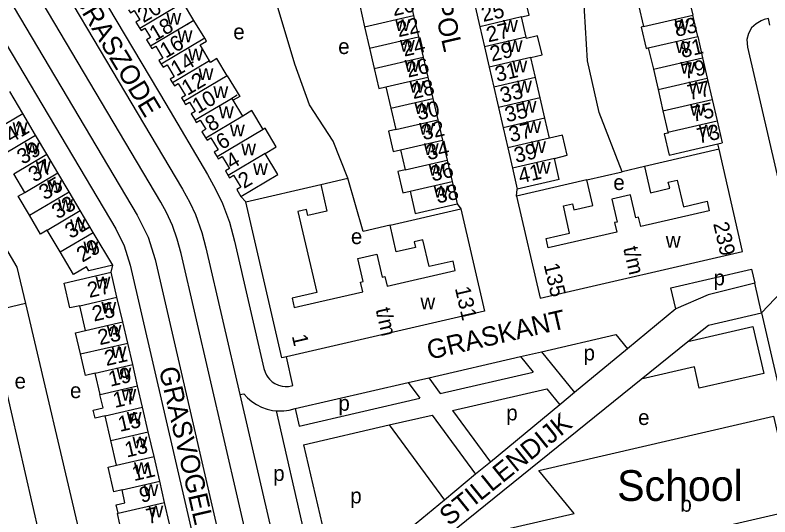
# Model space of a CAD drawing. Extents: x 155696 to 157795, y 382328 to 384028.
# Drawn here: x 156827.2 to 157023.6, y 383450.5 to 383581.1 of the extents above; entities that cross this region are included whole.
import ezdxf

# ---------------------------------------------------------------- set-up
doc = ezdxf.new("R2010")
doc.units = 0
for name, color, linetype in [('BLT_Basislijn', 7, 'Continuous'), ('BLT_Bebouwing', 7, 'Continuous'), ('BLT_Bebouwing_beschrifting', 7, 'Continuous'), ('BLT_Centroide', 7, 'Continuous'), ('BLT_Huisnummer', 7, 'Continuous'), ('BLT_Huisnummer_ tussenligend', 7, 'Continuous'), ('BLT_Huisnummer_reeks', 7, 'Continuous'), ('BLT_Onderverdeling_panden', 7, 'Continuous'), ('BLT_Straatnaam', 7, 'Continuous'), ('BLT_Vlakafsluiter', 7, 'Continuous')]:
    doc.layers.add(name, color=color, linetype=linetype)

msp = doc.modelspace()

# ---------------------------------------------------------------- linework, layer by layer
at = {"layer": 'BLT_Basislijn'}
for p, q in [((157010.4, 383546.2), (157010.08, 383547.6)), ((156991.02, 383541.71), (156985.17, 383540.36)), ((156813.06, 383540.07), (156827.64, 383515.53)), ((156976.01, 383538.25), (156985.17, 383540.36)), ((156906.74, 383537.03), (156913.76, 383538.66)), ((156917.76, 383524.82), (156913.76, 383538.66)), ((156957.68, 383534.02), (156957.88, 383535.82)), ((156887.21, 383532.52), (156885.94, 383533.92)), ((156942.23, 383532.02), (156943.16, 383530.67)), ((156924.78, 383526.43), (156917.76, 383524.82)), ((156852.19, 383514.18), (156852.6, 383515.97)), ((156827.64, 383515.53), (156829.86, 383506.04)), ((157021.46, 383503.61), (157019.76, 383511.33)), ((156829.86, 383506.04), (156820.23, 383503.79)), ((156829.86, 383506.04), (156847.51, 383431.01)), ((156837.46, 383428.77), (156820.23, 383503.79)), ((156958.72, 383492.19), (156962.01, 383488.17)), ((156964.15, 383493.44), (156972.82, 383482.87)), ((156937.81, 383482.58), (156962.01, 383488.17)), ((156934.82, 383486.67), (156937.81, 383482.58)), ((156929.51, 383485.44), (156932.51, 383481.35)), ((156941.03, 383478.19), (156965.55, 383483.85)), ((156965.55, 383483.85), (156968.96, 383479.68)), ((156901.15, 383474.11), (156932.51, 383481.35)), ((156900.1, 383478.65), (156901.15, 383474.11)), ((156895.09, 383478.09), (156906.54, 383428.52)), ((156924.57, 383474.39), (156935.73, 383476.96)), ((156935.73, 383476.96), (156947.03, 383461.55)), ((156941.03, 383478.19), (156950.89, 383464.75)), ((156902.27, 383469.24), (156924.57, 383474.39)), ((156924.57, 383474.39), (156938.91, 383454.84)), ((156902.27, 383469.24), (156910.94, 383431.72))]:
    msp.add_line(p, q, dxfattribs=at)
for points in [[(156985.17, 383540.36), (156979.21, 383555.75), (156976.12, 383569.24), (156975.14, 383586.64), (156972.66, 383601.42), (156967.79, 383615.59), (156962.86, 383637.18)], [(156819.05, 383622.9), (156870.75, 383535.77), (156872.62, 383532.3), (156874.14, 383529.17), (156875.78, 383524.53), (156876.84, 383520.56)], [(156830.06, 383623.03), (156830.96, 383618.27), (156832.24, 383615.56), (156866.39, 383558), (156877.28, 383539.64), (156879.37, 383535.8), (156881.18, 383532.03), (156882.95, 383527.19), (156884.25, 383522.27), (156891.92, 383489.07), (156892.22, 383488.12), (156892.6, 383487.38), (156892.95, 383486.88), (156893.38, 383486.33), (156894.12, 383485.66), (156894.79, 383485.21), (156895.73, 383484.76), (156896.68, 383484.52), (156897.5, 383484.43), (156898.35, 383484.44), (156899.11, 383484.58), (156899.5, 383484.67), (156897.77, 383492.17)], [(156983.21, 383030.72), (156967.38, 383099.24), (156870.41, 383519.08), (156869.37, 383522.79), (156868.15, 383526.38), (156866.54, 383529.72), (156865.07, 383532.4), (156812.59, 383620.85)], [(156804.51, 383617.81), (156812.22, 383604.81), (156813.61, 383602.86), (156815.47, 383601.09), (156816.82, 383599.81), (156817.73, 383598.46), (156858.93, 383529.03), (156861.8, 383523.32), (156863.59, 383517.5), (156885.15, 383424.18), (156889.03, 383407.35)], [(156800.07, 383613.67), (156800.58, 383613.17), (156801.11, 383612.63), (156801.9, 383611.42), (156807.49, 383602), (156810.35, 383597.97), (156853.37, 383525.46), (156855.54, 383521.06), (156857.16, 383516.02), (156880.47, 383415.1), (156880.62, 383413.68), (156880.33, 383411.87), (156879.52, 383410.29), (156878.8, 383409.4), (156877.87, 383408.71), (156877.29, 383411.17)], [(156913.76, 383538.66), (156909.99, 383548.33), (156903.82, 383557.78), (156899.97, 383568.38), (156893.8, 383589.01)], [(157023.66, 383578.52), (157023.27, 383580.23), (157022.19, 383579.96), (157021.34, 383579.68), (157020.04, 383578.87), (157018.83, 383577.79), (157018.05, 383576.3), (157017.68, 383574.81), (157017.8, 383572.79), (157028.71, 383525.55)], [(156876.84, 383520.56), (156885.68, 383482.29)], [(156999.14, 383504.62), (156997.86, 383510.15), (157018.83, 383515), (157019.76, 383511.33)], [(157019.76, 383511.33), (157007.58, 383508.26), (156999.14, 383504.62)], [(156999.14, 383504.62), (156986.6, 383494.26)], [(157007.65, 383500.41), (157021.46, 383503.61)], [(157021.46, 383503.61), (157033.62, 383450.98)], [(157002.3, 383496.1), (157019.22, 383500.01), (157022.03, 383487.83), (157005.27, 383483.96), (157003.99, 383489.51), (156990.17, 383486.32)], [(157002.3, 383496.1), (157007.65, 383500.41)], [(156964.15, 383493.44), (156983.57, 383497.93), (156986.6, 383494.26)], [(156990.17, 383486.32), (157002.3, 383496.1)], [(156986.6, 383494.26), (156972.82, 383482.87)], [(156934.82, 383486.67), (156958.72, 383492.19)], [(156958.72, 383492.19), (156964.15, 383493.44)], [(156911.34, 383422.73), (156990.17, 383486.32)], [(156929.51, 383485.44), (156934.82, 383486.67)], [(156900.1, 383478.65), (156929.51, 383485.44)], [(156885.68, 383482.29), (156886.75, 383482.53), (156887.69, 383481.48), (156888.78, 383480.53), (156890, 383479.7), (156891.33, 383479.02), (156892.74, 383478.51), (156894.2, 383478.18), (156895.09, 383478.09)], [(156885.68, 383482.29), (156898.85, 383425.26)], [(156972.82, 383482.87), (156968.96, 383479.68)], [(156895.09, 383478.09), (156895.67, 383478.04), (156897.12, 383478.08), (156898.51, 383478.28)], [(156898.51, 383478.28), (156900.1, 383478.65)], [(156968.96, 383479.68), (156950.89, 383464.75)], [(156950.89, 383464.75), (156947.03, 383461.55)], [(156947.03, 383461.55), (156938.91, 383454.84)], [(156938.91, 383454.84), (156910.94, 383431.72)]]:
    msp.add_lwpolyline(points, dxfattribs=at)
at = {"layer": 'BLT_Bebouwing'}
for p, q in [((156929.63, 383586.59), (156930.91, 383581.04)), ((157002.28, 383586.66), (157003.56, 383581.11)), ((156916.86, 383583.64), (156918.14, 383578.08)), ((156946.89, 383583.38), (156948.11, 383578.12)), ((156989.46, 383583.7), (156990.71, 383578.14)), ((156930.91, 383581.04), (156932.19, 383575.48)), ((156960.24, 383575.38), (156959.02, 383580.64)), ((157004.85, 383575.55), (157003.56, 383581.11)), ((156873.52, 383579.6), (156871.84, 383578.6)), ((156876.52, 383575.1), (156873.73, 383579.73)), ((156918.14, 383578.08), (156919.41, 383572.53)), ((156948.11, 383578.12), (156949.32, 383572.86)), ((156932.19, 383575.48), (156933.41, 383570.22)), ((157004.85, 383575.55), (157006.13, 383570)), ((156949.32, 383572.86), (156950.54, 383567.6)), ((156919.41, 383572.53), (156920.62, 383567.27)), ((156991.41, 383572.44), (156991.98, 383572.58)), ((156933.41, 383570.22), (156934.63, 383564.96)), ((156962.67, 383564.86), (156961.45, 383570.12)), ((157006.13, 383570), (157007.35, 383564.74)), ((156950.54, 383567.6), (156951.75, 383562.34)), ((156993.31, 383567.04), (156994.53, 383561.78)), ((156934.63, 383564.96), (156935.92, 383559.41)), ((156963.88, 383559.59), (156962.67, 383564.86)), ((157007.35, 383564.74), (157008.63, 383559.18)), ((156829.14, 383555.52), (156825.77, 383561.2)), ((156923.71, 383562.44), (156925, 383556.88)), ((156951.75, 383562.34), (156952.71, 383558.18)), ((156994.53, 383561.78), (156995.78, 383556.21)), ((156885, 383560.25), (156883.32, 383559.25)), ((156886.44, 383554.82), (156883.96, 383558.95)), ((156935.92, 383559.41), (156937.19, 383553.85)), ((156965.1, 383554.33), (156963.88, 383559.59)), ((157008.63, 383559.18), (157009.91, 383553.63)), ((156925, 383556.88), (156926.28, 383551.33)), ((156952.71, 383558.18), (156952.97, 383557.07)), ((156952.97, 383557.07), (156953.93, 383552.92)), ((156832.51, 383549.85), (156829.14, 383555.52)), ((156995.78, 383556.21), (156997.06, 383550.66)), ((156937.19, 383553.85), (156938.41, 383548.59)), ((156966.31, 383549.07), (156965.1, 383554.33)), ((157009.91, 383553.63), (157011.24, 383547.87)), ((156953.93, 383552.92), (156954.19, 383551.81)), ((156954.19, 383551.81), (156955.4, 383546.55)), ((156835.42, 383544.94), (156832.51, 383549.85)), ((156938.41, 383548.59), (156939.62, 383543.33)), ((157000.33, 383545.35), (157010.08, 383547.6)), ((157010.08, 383547.6), (157011.24, 383547.87)), ((156927.49, 383546.07), (156928.71, 383540.81)), ((156955.4, 383546.55), (156956.62, 383541.29)), ((157010.4, 383546.2), (156991.02, 383541.71)), ((156838.32, 383540.04), (156835.42, 383544.94)), ((156939.62, 383543.33), (156940.9, 383537.77)), ((156968.79, 383538.34), (156967.53, 383543.81)), ((156956.62, 383541.29), (156957.88, 383535.82)), ((156829.72, 383534.94), (156826.82, 383539.84)), ((156841.23, 383535.14), (156838.32, 383540.04)), ((156940.9, 383537.77), (156942.23, 383532.02)), ((156976.01, 383538.25), (156957.68, 383534.02)), ((156968.79, 383538.34), (156957.88, 383535.82)), ((156887.21, 383532.52), (156906.74, 383537.03)), ((156844.14, 383530.24), (156841.23, 383535.14)), ((156929.99, 383535.25), (156931.32, 383529.49)), ((156931.32, 383529.5), (156942.23, 383532.02)), ((156847.51, 383524.56), (156844.14, 383530.24)), ((156924.78, 383526.43), (156943.16, 383530.67)), ((156838.91, 383519.46), (156835.54, 383525.14)), ((156852.6, 383515.97), (156847.51, 383524.56)), ((156853.69, 383507.69), (156852.19, 383514.18)), ((156855.23, 383501.28), (156853.69, 383507.69)), ((156845.48, 383499.03), (156844, 383505.46)), ((156856.51, 383495.72), (156855.23, 383501.28)), ((156857.79, 383490.17), (156856.51, 383495.72)), ((156859.07, 383484.61), (156857.79, 383490.17)), ((156849.33, 383482.36), (156848.05, 383487.92)), ((156860.36, 383479.06), (156859.07, 383484.61)), ((156861.84, 383472.63), (156860.36, 383479.06)), ((156852.1, 383470.38), (156850.61, 383476.81)), ((156863.33, 383466.2), (156861.84, 383472.63)), ((156864.81, 383459.77), (156863.33, 383466.2)), ((156866.09, 383454.21), (156864.81, 383459.77)), ((156867.38, 383448.66), (156866.09, 383454.21)), ((156853.78, 383451.37), (156854.01, 383451.42))]:
    msp.add_line(p, q, dxfattribs=at)
for points in [[(156959.02, 383580.64), (156960.95, 383581.08), (156959.73, 383586.35)], [(156856.69, 383582.52), (156857.18, 383581.7), (156858.2, 383582.32), (156859.65, 383579.91), (156858.63, 383579.3), (156859.63, 383577.64)], [(156873.73, 383579.73), (156871.03, 383584.22), (156869.38, 383583.22), (156869.29, 383583.37)], [(156859.63, 383577.64), (156859.97, 383577.08), (156860.98, 383577.69), (156862.43, 383575.29), (156861.41, 383574.67), (156862.41, 383573)], [(156990.71, 383578.14), (156990.14, 383578.01), (156991.41, 383572.44)], [(156877.8, 383569.23), (156875.32, 383573.35), (156876.98, 383574.35), (156876.52, 383575.1)], [(156961.45, 383570.12), (156964.34, 383570.78), (156963.19, 383575.72), (156960.32, 383575.06), (156960.24, 383575.38)], [(156862.41, 383573), (156862.74, 383572.44), (156863.77, 383573.06), (156865.65, 383569.94), (156864.61, 383569.32), (156865.19, 383568.38)], [(156991.98, 383572.58), (156993.31, 383567.04)], [(156882.4, 383565.33), (156879.69, 383569.82), (156878.04, 383568.83), (156877.8, 383569.23)], [(156865.19, 383568.38), (156865.69, 383567.57), (156866.71, 383568.18), (156868.58, 383565.08), (156867.54, 383564.45), (156868.13, 383563.49)], [(156920.62, 383567.27), (156921.83, 383562.01), (156923.71, 383562.44)], [(156882.4, 383565.33), (156885.64, 383559.95), (156883.96, 383558.95)], [(156868.13, 383563.49), (156868.62, 383562.7), (156869.64, 383563.31), (156871.52, 383560.2), (156870.48, 383559.57), (156871.06, 383558.61)], [(156871.06, 383558.61), (156871.55, 383557.81), (156872.58, 383558.43), (156874.03, 383556.03), (156872.99, 383555.4), (156874.01, 383553.73)], [(156891.73, 383551.34), (156888.79, 383556.26), (156886.44, 383554.82)], [(156874.01, 383553.73), (156874.34, 383553.18), (156875.37, 383553.8), (156876.82, 383551.39), (156875.76, 383550.75), (156876.78, 383549.09)], [(156892.3, 383545.05), (156895.16, 383546.79), (156892.25, 383551.65), (156891.73, 383551.34)], [(156926.28, 383551.33), (156924.39, 383550.89), (156925.6, 383545.63), (156927.49, 383546.07)], [(156876.78, 383549.09), (156877.12, 383548.55), (156878.15, 383549.18), (156880.04, 383546.05), (156878.99, 383545.42), (156879.73, 383544.22)], [(156967.53, 383543.81), (156970.85, 383544.62), (156969.65, 383549.86), (156966.31, 383549.07)], [(156997.06, 383550.66), (156997.12, 383550.43), (156996.14, 383550.21), (156997.41, 383544.67), (157000.33, 383545.35)], [(156957.68, 383534.02), (156963.83, 383507.42), (157016.54, 383519.6), (157010.4, 383546.2)], [(156879.73, 383544.22), (156880.06, 383543.68), (156881.09, 383544.3), (156882.98, 383541.16), (156881.95, 383540.54), (156882.67, 383539.33)], [(156885.94, 383533.92), (156895.55, 383539.63), (156892.3, 383545.05)], [(156991.02, 383541.71), (156992.59, 383534.89), (156997.56, 383536.04), (156997.2, 383537.6), (156999.54, 383538.14), (157001.14, 383531.22), (157007.28, 383532.64), (157007.84, 383530.2), (156990.01, 383526.08), (156989.45, 383528.52), (156988.76, 383528.36), (156987.39, 383534.31), (156982.52, 383533.18), (156983.89, 383527.24), (156983.21, 383527.08), (156983.77, 383524.64), (156965.94, 383520.52), (156965.38, 383522.96), (156971.52, 383524.38), (156969.89, 383531.44), (156972.22, 383531.98), (156972.58, 383530.42), (156977.55, 383531.57), (156976.01, 383538.25)], [(156882.67, 383539.33), (156883, 383538.79), (156884.03, 383539.41), (156885.9, 383536.31), (156884.86, 383535.68), (156885.94, 383533.92)], [(156928.71, 383540.81), (156926.81, 383540.37), (156928.1, 383534.82), (156929.99, 383535.25)], [(156906.74, 383537.03), (156908.35, 383530.07), (156903.37, 383528.92), (156902.99, 383530.54), (156900.78, 383530.02), (156905.67, 383508.88), (156899.25, 383507.4), (156899.82, 383504.96), (156906.24, 383506.45), (156917.65, 383509.08), (156917.06, 383511.61), (156917.74, 383511.77), (156916.36, 383517.76), (156921.36, 383518.91), (156922.74, 383512.92), (156923.43, 383513.08), (156924.01, 383510.54), (156941.74, 383514.63), (156941.18, 383517.07), (156934.95, 383515.63), (156933.33, 383522.64), (156931.04, 383522.12), (156931.38, 383520.64), (156926.38, 383519.48), (156924.78, 383526.43)], [(156830.88, 383529), (156827.94, 383533.96), (156829.72, 383534.94)], [(156897.77, 383492.16), (156896.6, 383491.89), (156887.21, 383532.52)], [(156943.16, 383530.67), (156949.31, 383504.07), (156897.77, 383492.16)], [(156835.54, 383525.14), (156833.79, 383524.1), (156830.88, 383529)], [(156852.6, 383515.97), (156846.39, 383514.54), (156845.76, 383515.6), (156842.39, 383513.6), (156838.91, 383519.46)], [(156844, 383505.46), (156841.41, 383504.86), (156839.91, 383511.35), (156852.19, 383514.18)], [(156844.19, 383492.88), (156842.91, 383498.43), (156845.48, 383499.03)], [(156848.05, 383487.92), (156845.48, 383487.29), (156844.19, 383492.88)], [(156850.61, 383476.81), (156847.99, 383476.2), (156847.51, 383478.26), (156850.06, 383478.85), (156849.25, 383482.35), (156849.33, 383482.36)], [(156853.58, 383463.95), (156852.1, 383470.38)], [(156855.07, 383457.52), (156852.87, 383457.01), (156851.39, 383463.44), (156853.58, 383463.95)], [(156854.01, 383451.42), (156853.5, 383453.63), (156855.76, 383454.15), (156855.07, 383457.52)], [(156857.63, 383446.41), (156855.06, 383445.82), (156853.78, 383451.37)]]:
    msp.add_lwpolyline(points, dxfattribs=at)
msp.add_lwpolyline([(156963.49, 383462.53), (157024.61, 383476.65), (157030.25, 383452.25), (156920.89, 383426.99), (156941.26, 383444.13), (156972.68, 383451.38)], close=True, dxfattribs=at)
at = {"layer": 'BLT_Onderverdeling_panden'}
for p, q in [((156869.29, 383583.37), (156859.63, 383577.64)), ((156918.14, 383578.08), (156930.91, 383581.04)), ((156959.02, 383580.64), (156948.11, 383578.12)), ((156990.71, 383578.14), (157003.56, 383581.11)), ((156873.73, 383579.73), (156862.41, 383573)), ((156876.52, 383575.1), (156865.19, 383568.38)), ((156919.41, 383572.53), (156932.19, 383575.48)), ((156960.24, 383575.38), (156949.32, 383572.86)), ((156991.98, 383572.58), (157004.85, 383575.55)), ((156877.8, 383569.23), (156868.13, 383563.49)), ((156920.62, 383567.27), (156933.41, 383570.22)), ((156961.45, 383570.12), (156950.54, 383567.6)), ((156993.31, 383567.04), (157006.13, 383570)), ((156882.4, 383565.33), (156871.06, 383558.61)), ((156923.71, 383562.44), (156934.63, 383564.96)), ((156962.67, 383564.86), (156951.75, 383562.34)), ((156994.53, 383561.78), (157007.35, 383564.74)), ((156925, 383556.88), (156935.92, 383559.41)), ((156963.88, 383559.59), (156952.97, 383557.07)), ((156995.78, 383556.21), (157008.63, 383559.18)), ((156820.54, 383550.42), (156829.14, 383555.52)), ((156886.44, 383554.82), (156876.78, 383549.09)), ((156926.28, 383551.33), (156937.19, 383553.85)), ((156965.1, 383554.33), (156954.19, 383551.81)), ((156997.06, 383550.66), (157009.91, 383553.63)), ((156891.73, 383551.34), (156879.73, 383544.22)), ((156823.91, 383544.74), (156832.51, 383549.85)), ((156966.31, 383549.07), (156955.4, 383546.55)), ((156927.49, 383546.07), (156938.41, 383548.59)), ((156826.82, 383539.84), (156835.42, 383544.94)), ((156892.3, 383545.05), (156882.67, 383539.33)), ((156928.71, 383540.81), (156939.62, 383543.33)), ((156967.53, 383543.81), (156956.62, 383541.29)), ((156829.72, 383534.94), (156838.32, 383540.04)), ((156929.99, 383535.25), (156940.9, 383537.77)), ((156830.88, 383529), (156841.23, 383535.14)), ((156835.54, 383525.14), (156844.14, 383530.24)), ((156838.91, 383519.46), (156847.51, 383524.56)), ((156844, 383505.46), (156853.69, 383507.69)), ((156845.48, 383499.03), (156855.23, 383501.28)), ((156844.19, 383492.88), (156856.51, 383495.72)), ((156848.05, 383487.92), (156857.79, 383490.17)), ((156849.33, 383482.36), (156859.07, 383484.61)), ((156850.61, 383476.81), (156860.36, 383479.06)), ((156852.1, 383470.38), (156861.84, 383472.63)), ((156853.58, 383463.95), (156863.33, 383466.2)), ((156855.07, 383457.52), (156864.81, 383459.77)), ((156854.01, 383451.42), (156866.09, 383454.21))]:
    msp.add_line(p, q, dxfattribs=at)
msp.add_lwpolyline([(156883.96, 383558.95), (156883.66, 383559.45), (156874.01, 383553.73)], dxfattribs=at)
at = {"layer": 'BLT_Vlakafsluiter'}
msp.add_line((157035.44, 383518.36), (157021.46, 383503.61), dxfattribs=at)

# ---------------------------------------------------------------- texts
at = {"layer": 'BLT_Bebouwing_beschrifting'}
msp.add_text('School', height=8, dxfattribs=at).set_placement((156983.88, 383454.62))
at = {"layer": 'BLT_Centroide'}
for s, p in [('w', (156866.56, 383578.62)), ('w', (156926.09, 383577)), ('w', (156954.17, 383576.75)), ('w', (156998.75, 383577.06)), ('w', (156869.46, 383574.06)), ('e', (156883.96, 383574.82)), ('w', (156927.34, 383571.59)), ('w', (156955.39, 383571.5)), ('e', (156911.27, 383570.99)), ('w', (156999.06, 383571.28)), ('w', (156872.24, 383569.31)), ('w', (156928.56, 383566.34)), ('w', (156956.61, 383566.22)), ('w', (157000.33, 383565.88)), ('w', (156874.93, 383564.22)), ('w', (156929.81, 383560.91)), ('w', (156957.82, 383560.97)), ('w', (157002.53, 383560.69)), ('w', (156878.78, 383559.53)), ('w', (156880.22, 383554.28)), ('w', (156931.09, 383555.38)), ('w', (156959.03, 383555.72)), ('w', (157002.84, 383554.94)), ('w', (156826.52, 383550.12)), ('w', (156932.34, 383549.97)), ('w', (156960.25, 383550.44)), ('w', (156883.09, 383549.53)), ('w', (157005.12, 383549.5)), ('w', (156829.66, 383544.84)), ('w', (156886.02, 383544.62)), ('w', (156933.56, 383544.69)), ('w', (156961.47, 383545.19)), ('w', (156832.57, 383539.94)), ('w', (156889.11, 383539.47)), ('w', (156934.8, 383539.28)), ('w', (156962.7, 383539.81)), ('w', (156835.48, 383535.03)), ('e', (156982.88, 383535.58)), ('w', (156936.11, 383533.62)), ('w', (156838.38, 383530.12)), ('w', (156841.52, 383524.84)), ('e', (156914.58, 383521.5)), ('w', (156996.54, 383520.53)), ('w', (156844.95, 383519.09)), ('p', (157008.96, 383510.75)), ('w', (156848.1, 383509.91)), ('w', (156849.62, 383503.38)), ('w', (156932.66, 383504.51)), ('w', (156850.99, 383497.38)), ('w', (156852.27, 383491.81)), ('p', (156975.13, 383491.21)), ('w', (156853.55, 383486.25)), ('e', (156827.03, 383483.86)), ('e', (156841.46, 383481.38)), ('w', (156854.84, 383480.72)), ('p', (156911.32, 383478.1)), ('p', (156955.01, 383475.59)), ('w', (156856.23, 383474.72)), ('e', (156989.34, 383474.39)), ('w', (156857.71, 383468.28)), ('w', (156858.1, 383461.59)), ('p', (156894.35, 383459.82)), ('w', (156860.59, 383455.88)), ('p', (156914.41, 383453.99)), ('b', (157000.34, 383451.81)), ('w', (156861.87, 383450.31))]:
    msp.add_text(s, height=4, dxfattribs=at).set_placement(p)
at = {"layer": 'BLT_Huisnummer'}
for s, rotation, p in [('25', 13.0065, (156949.02, 383579.33)), ('22', 13.0066, (156926.98, 383575.36)), ('18', 30.6833, (156863.63, 383574.23)), ('81', 13.0063, (157000.82, 383569.92)), ('29', 13.0065, (156951.24, 383569.01)), ('14', 30.6833, (156869.18, 383565.06)), ('26', 13.0066, (156929.46, 383564.83)), ('33', 13.0065, (156953.89, 383558.25)), ('77', 13.0063, (157002.68, 383558.94)), ('10', 30.6833, (156874.76, 383555.35)), ('30', 13.0066, (156932.2, 383553.71)), ('41', 30.681, (156826.11, 383547.71)), ('37', 13.0065, (156956.18, 383548.02)), ('73', 13.0063, (157005.15, 383547.64)), ('6', 30.6833, (156880.95, 383545.93)), ('34', 13.0066, (156934.69, 383543.33)), ('37', 30.681, (156832.13, 383537.47)), ('41', 13.0065, (156958.66, 383537.26)), ('2', 30.6833, (156886.73, 383535.83)), ('38', 13.0066, (156937.13, 383532.03)), ('33', 30.681, (156838.23, 383527.86)), ('29', 30.681, (156844.68, 383516.62)), ('27', 13.0023, (156846.49, 383507.47)), ('21', 13.0023, (156850.92, 383489.73)), ('17', 13.0023, (156853.13, 383478.82)), ('13', 13.0023, (156856.21, 383465.9)), ('9', 13.0023, (156860, 383454.11))]:
    msp.add_text(s, height=4, rotation=rotation, dxfattribs=at).set_placement(p)
at = {"layer": 'BLT_Huisnummer_ tussenligend'}
for s, rotation, p in [('20', 30.6833, (156860.56, 383578.99)), ('20', 13.0066, (156925.73, 383580.84)), ('83', 13.0063, (156999.26, 383575.44)), ('27', 13.0065, (156950.33, 383574.02)), ('16', 30.6833, (156866.36, 383569.76)), ('24', 13.0066, (156928.47, 383570.29)), ('31', 13.0065, (156952.59, 383563.72)), ('79', 13.0063, (157001.48, 383564.42)), ('12', 30.6833, (156872, 383560.06)), ('28', 13.0066, (156930.83, 383559.24)), ('35', 13.0065, (156955.14, 383553.22)), ('75', 13.0063, (157003.62, 383553.27)), ('8', 30.6833, (156878.15, 383550.64)), ('32', 13.0066, (156933.47, 383548.52)), ('39', 30.681, (156829.16, 383542.09)), ('39', 13.0065, (156957.54, 383542.61)), ('4', 30.6833, (156883.52, 383540.85)), ('36', 13.0066, (156935.8, 383537.78)), ('35', 30.681, (156834.88, 383532.82)), ('31', 30.681, (156841.65, 383522.77)), ('25', 13.0023, (156847.71, 383501.31)), ('23', 13.0023, (156849.19, 383495.16)), ('19', 13.0023, (156851.96, 383484.35)), ('15', 13.0023, (156854.44, 383472.58)), ('11', 13.0023, (156858.12, 383459.75)), ('7', 13.0023, (156861.78, 383448.54))]:
    msp.add_text(s, height=4, rotation=rotation, dxfattribs=at).set_placement(p)
at = {"layer": 'BLT_Huisnummer_reeks'}
for s, rotation, p in [('239', 283.0146, (157008.85, 383526.83)), ('t/m', 283.0146, (156985.43, 383520.45)), ('135', 283.0146, (156964.73, 383516.13)), ('131', 283.0121, (156941.62, 383510.03)), ('t/m', 283.0121, (156920.99, 383504.48)), ('1', 283.0121, (156899.17, 383497.56))]:
    msp.add_text(s, height=4, rotation=rotation, dxfattribs=at).set_placement(p)
at = {"layer": 'BLT_Straatnaam'}
for s, rotation, p in [('GRASPOL', 283.0067, (156931.61, 383602.76)), ('GRASZODE', 301.0948, (156841.74, 383586.27)), ('GRASKANT', 13.0064, (156935.01, 383491.36)), ('GRASVOGEL', 283.0054, (156864.55, 383488.99)), ('STILLENDIJK', 38.8883, (156940.15, 383447.94))]:
    msp.add_text(s, height=5, rotation=rotation, dxfattribs=at).set_placement(p)

doc.saveas('drawing.dxf')
